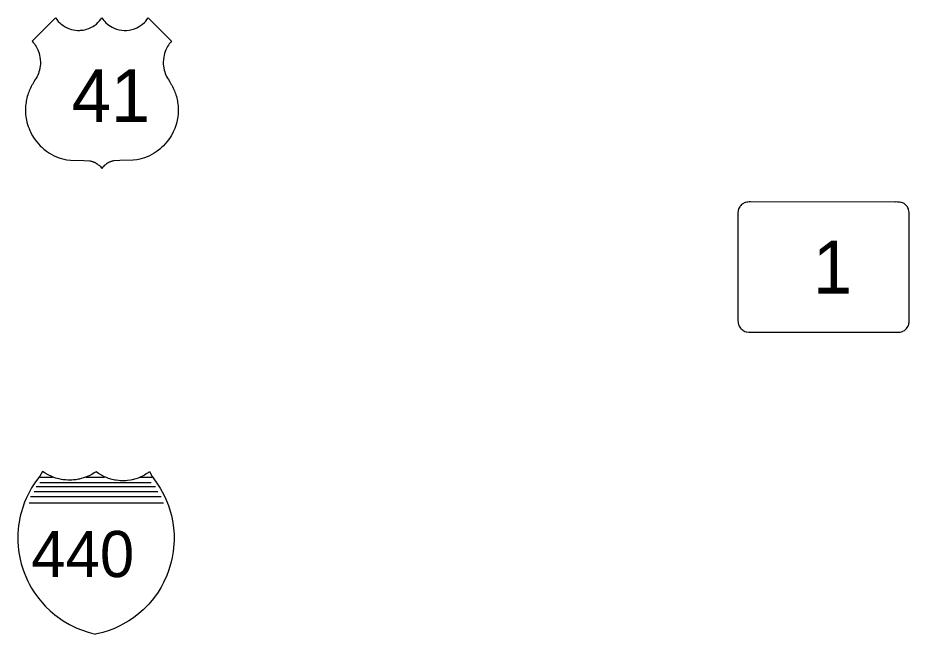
# Model space of a CAD drawing. Extents: x 1612280 to 1883141, y 560852 to 780851.
# Drawn here: x 1750959 to 1758104, y 653332 to 658270 of the extents above; entities that cross this region are included whole.
import ezdxf

# ---------------------------------------------------------------- set-up
doc = ezdxf.new("R2010")
doc.units = 0
for name, color, linetype in [('DESIGN - ROW - Slope Lines', 7, 'Continuous'), ('SURVEY - DRAINAGE - Bridge Deck with Text', 7, 'Continuous'), ('SURVEY - DRAINAGE - Bridge Hydraulic Data with Text', 7, 'Continuous')]:
    doc.layers.add(name, color=color, linetype=linetype)

msp = doc.modelspace()

# ---------------------------------------------------------------- linework, layer by layer
at = {"layer": 'DESIGN - ROW - Slope Lines'}
msp.add_line((1756730.7, 656692.9), (1756730.7, 655861.1), dxfattribs=at)
msp.add_line((1756730.7, 656692.9), (1756730.7, 655861.1), dxfattribs=at)
for points in [[(1758103.6, 656682.5), (1758103.5, 656690.2), (1758103.3, 656698.3), (1758102.3, 656712.9), (1758100.9, 656723.4), (1758099.1, 656734.2), (1758097.1, 656740.1), (1758093.9, 656746.7), (1758089.5, 656754.2), (1758084.1, 656761.6), (1758079.4, 656767), (1758073.5, 656772.6), (1758068.8, 656776.4), (1758062.4, 656780.9), (1758057.4, 656783.9), (1758049.1, 656787.9), (1758043, 656790), (1758035.8, 656791.4), (1758026.5, 656792.8), (1758018.4, 656793.6), (1758009.7, 656794.2), (1757997.4, 656794.3), (1757988, 656793.6), (1756830.7, 656794.3), (1756821.3, 656794.3), (1756811, 656793.6), (1756801.9, 656792.5), (1756792.8, 656790.8), (1756788.5, 656789.5), (1756781.3, 656786.4), (1756774.9, 656783.1), (1756769.6, 656779.8), (1756760.7, 656773), (1756754.6, 656767.2), (1756749.5, 656761.3), (1756745.6, 656756), (1756739.8, 656746.4), (1756736.4, 656739.1), (1756734.5, 656733.9), (1756733.8, 656730.1), (1756733.3, 656726.8), (1756732.4, 656719.6), (1756731.3, 656710.2), (1756730.9, 656702.3), (1756730.8, 656695.6), (1756730.7, 656677.7)], [(1758103.6, 656682.5), (1758103.5, 656690.2), (1758103.3, 656698.3), (1758102.3, 656712.9), (1758100.9, 656723.4), (1758099.1, 656734.2), (1758097.1, 656740.1), (1758093.9, 656746.7), (1758089.5, 656754.2), (1758084.1, 656761.6), (1758079.4, 656767), (1758073.5, 656772.6), (1758068.8, 656776.4), (1758062.4, 656780.9), (1758057.4, 656783.9), (1758049.1, 656787.9), (1758043, 656790), (1758035.8, 656791.4), (1758026.5, 656792.8), (1758018.4, 656793.6), (1758009.7, 656794.2), (1757997.4, 656794.3), (1757988, 656793.6), (1756830.7, 656794.3), (1756821.3, 656794.3), (1756811, 656793.6), (1756801.9, 656792.5), (1756792.8, 656790.8), (1756788.5, 656789.5), (1756781.3, 656786.4), (1756774.9, 656783.1), (1756769.6, 656779.8), (1756760.7, 656773), (1756754.6, 656767.2), (1756749.5, 656761.3), (1756745.6, 656756), (1756739.8, 656746.4), (1756736.4, 656739.1), (1756734.5, 656733.9), (1756733.8, 656730.1), (1756733.3, 656726.8), (1756732.4, 656719.6), (1756731.3, 656710.2), (1756730.9, 656702.3), (1756730.8, 656695.6), (1756730.7, 656677.7)], [(1757993.7, 655751.8), (1758014.4, 655752.1), (1758031.4, 655752.4), (1758041.7, 655754.8), (1758053.9, 655759.6), (1758065.1, 655766), (1758074, 655772.9), (1758082.1, 655780.9), (1758088.3, 655788.8), (1758094.3, 655798.6), (1758097.9, 655806.4), (1758100.5, 655813.4), (1758102.1, 655821), (1758102.9, 655829.2), (1758103.2, 655839.2), (1758103.6, 655862.5), (1758103.6, 656682.5)], [(1757993.7, 655751.8), (1758014.4, 655752.1), (1758031.4, 655752.4), (1758041.7, 655754.8), (1758053.9, 655759.6), (1758065.1, 655766), (1758074, 655772.9), (1758082.1, 655780.9), (1758088.3, 655788.8), (1758094.3, 655798.6), (1758097.9, 655806.4), (1758100.5, 655813.4), (1758102.1, 655821), (1758102.9, 655829.2), (1758103.2, 655839.2), (1758103.6, 655862.5), (1758103.6, 656682.5)], [(1756730.7, 655861.1), (1756730.9, 655852.1), (1756731.4, 655842), (1756732.2, 655832.5), (1756733.3, 655823.3), (1756734.7, 655814.1), (1756737.5, 655806.4), (1756740.9, 655799.2), (1756745.4, 655791.8), (1756750.8, 655784.5), (1756756.4, 655778.3), (1756763.7, 655771.7), (1756770.6, 655766.5), (1756778.6, 655761.7), (1756787.2, 655757.7), (1756796.1, 655754.6), (1756803.4, 655753.7), (1756818.3, 655752.5), (1756837.1, 655751.8), (1757993.7, 655751.8)], [(1756730.7, 655861.1), (1756730.9, 655852.1), (1756731.4, 655842), (1756732.2, 655832.5), (1756733.3, 655823.3), (1756734.7, 655814.1), (1756737.5, 655806.4), (1756740.9, 655799.2), (1756745.4, 655791.8), (1756750.8, 655784.5), (1756756.4, 655778.3), (1756763.7, 655771.7), (1756770.6, 655766.5), (1756778.6, 655761.7), (1756787.2, 655757.7), (1756796.1, 655754.6), (1756803.4, 655753.7), (1756818.3, 655752.5), (1756837.1, 655751.8), (1757993.7, 655751.8)]]:
    msp.add_lwpolyline(points, dxfattribs=at)
at = {"layer": 'SURVEY - DRAINAGE - Bridge Deck with Text'}
for points in [[(1751074.2, 658083.2), (1751261.7, 658269.6), (1751271.4, 658255.9), (1751283.7, 658241.1), (1751295.8, 658228.9), (1751307, 658219.1), (1751319.4, 658209.7), (1751332.2, 658201.3), (1751344.6, 658194.3), (1751359.2, 658187.4), (1751372.2, 658182.2), (1751388.6, 658177), (1751404.3, 658173.3), (1751420.8, 658170.7), (1751438.5, 658169.3), (1751446.5, 658169.1), (1751454.6, 658169.2), (1751462.4, 658169.6), (1751472.6, 658170.5), (1751482.9, 658172), (1751496.4, 658174.6), (1751508.9, 658177.8), (1751527.1, 658184), (1751544.3, 658191.5), (1751560.8, 658200.4), (1751574.7, 658209.4), (1751588.5, 658219.9), (1751601.7, 658231.8), (1751613.8, 658244.5), (1751625, 658258.4), (1751632.8, 658269.6), (1751639.7, 658259.7), (1751648.5, 658248.5), (1751656.4, 658239.5), (1751665.7, 658230.1), (1751677.4, 658219.7), (1751689.8, 658210.2), (1751703, 658201.6), (1751716.6, 658193.9), (1751732.6, 658186.4), (1751751.2, 658179.5), (1751772.5, 658173.9), (1751793.3, 658170.5), (1751811.5, 658169.2), (1751831.2, 658169.5), (1751851.5, 658171.6), (1751871.6, 658175.6), (1751894, 658182.4), (1751911.7, 658189.7), (1751926.3, 658197.1), (1751943.3, 658207.6), (1751957.5, 658218.2), (1751973.3, 658232.2), (1751984.1, 658243.5), (1751993.9, 658255.4), (1752004, 658269.7), (1752190.8, 658083.2)], [(1751074.2, 658083.2), (1751261.7, 658269.6), (1751271.4, 658255.9), (1751283.7, 658241.1), (1751295.8, 658228.9), (1751307, 658219.1), (1751319.4, 658209.7), (1751332.2, 658201.3), (1751344.6, 658194.3), (1751359.2, 658187.4), (1751372.2, 658182.2), (1751388.6, 658177), (1751404.3, 658173.3), (1751420.8, 658170.7), (1751438.5, 658169.3), (1751446.5, 658169.1), (1751454.6, 658169.2), (1751462.4, 658169.6), (1751472.6, 658170.5), (1751482.9, 658172), (1751496.4, 658174.6), (1751508.9, 658177.8), (1751527.1, 658184), (1751544.3, 658191.5), (1751560.8, 658200.4), (1751574.7, 658209.4), (1751588.5, 658219.9), (1751601.7, 658231.8), (1751613.8, 658244.5), (1751625, 658258.4), (1751632.8, 658269.6), (1751639.7, 658259.7), (1751648.5, 658248.5), (1751656.4, 658239.5), (1751665.7, 658230.1), (1751677.4, 658219.7), (1751689.8, 658210.2), (1751703, 658201.6), (1751716.6, 658193.9), (1751732.6, 658186.4), (1751751.2, 658179.5), (1751772.5, 658173.9), (1751793.3, 658170.5), (1751811.5, 658169.2), (1751831.2, 658169.5), (1751851.5, 658171.6), (1751871.6, 658175.6), (1751894, 658182.4), (1751911.7, 658189.7), (1751926.3, 658197.1), (1751943.3, 658207.6), (1751957.5, 658218.2), (1751973.3, 658232.2), (1751984.1, 658243.5), (1751993.9, 658255.4), (1752004, 658269.7), (1752190.8, 658083.2)], [(1751074.2, 658083.2), (1751083.3, 658072.5), (1751091.6, 658061.9), (1751099.2, 658050.7), (1751105.5, 658040.4), (1751112.3, 658028), (1751118.8, 658014.1), (1751124.4, 658000), (1751129.5, 657984.6), (1751133.4, 657970.2), (1751136.5, 657954.2), (1751138.8, 657936.5), (1751139.9, 657914.8), (1751139.6, 657898.4), (1751138.2, 657882.4), (1751136.1, 657868.4), (1751132.2, 657850.2), (1751128.3, 657836.4), (1751123.7, 657823.2), (1751118.8, 657811.1), (1751114, 657800.8), (1751106.3, 657787), (1751099, 657774.4), (1751088.5, 657756.8), (1751075.7, 657735.7), (1751072, 657729.7), (1751066, 657718.7), (1751059.5, 657705.5), (1751055.3, 657696.4), (1751050.5, 657685.1), (1751046.4, 657674.8), (1751042.5, 657663.8), (1751038.6, 657652.1), (1751034.9, 657639.5), (1751031.5, 657626.1), (1751028.9, 657614.9), (1751026.6, 657602.8), (1751024.7, 657590.9), (1751023, 657578.2), (1751021.8, 657566.6), (1751021, 657555.1), (1751020.5, 657544.2), (1751020.3, 657533.1), (1751020.4, 657520.6), (1751020.9, 657509), (1751021.9, 657494.5), (1751023.6, 657479.4), (1751025.8, 657464.1), (1751028.6, 657449.4), (1751032.3, 657433.1), (1751037.5, 657414), (1751042.2, 657399.4), (1751048.7, 657381.8), (1751054.6, 657368.2), (1751059.7, 657356.6), (1751067, 657342), (1751076.7, 657324.5), (1751085.9, 657309.8), (1751097.9, 657292.2), (1751110.4, 657275.9), (1751124.2, 657259.6), (1751138.7, 657244.3), (1751151.2, 657232.3), (1751168.1, 657217.6), (1751187.8, 657202.2), (1751212, 657185.9), (1751232.2, 657174.1), (1751251.7, 657164.2), (1751269.7, 657156.1), (1751290.5, 657148.1), (1751309.8, 657141.7), (1751329.2, 657136.4), (1751339, 657134.1), (1751351.7, 657132.4), (1751381.8, 657129.8), (1751487.4, 657126.5), (1751535.1, 657124), (1751539.6, 657123.5), (1751544.4, 657122.4), (1751549.6, 657121.1), (1751554.6, 657119.6), (1751559.4, 657118.1), (1751564, 657116.3), (1751569.3, 657114.2), (1751573.7, 657112.2), (1751578.8, 657109.7), (1751582.7, 657107.7), (1751586.7, 657105.4), (1751595.3, 657100), (1751604.4, 657093.3), (1751612.9, 657085.9), (1751620.6, 657078.4), (1751627, 657071.1), (1751632.5, 657062.8)], [(1751074.2, 658083.2), (1751083.3, 658072.5), (1751091.6, 658061.9), (1751099.2, 658050.7), (1751105.5, 658040.4), (1751112.3, 658028), (1751118.8, 658014.1), (1751124.4, 658000), (1751129.5, 657984.6), (1751133.4, 657970.2), (1751136.5, 657954.2), (1751138.8, 657936.5), (1751139.9, 657914.8), (1751139.6, 657898.4), (1751138.2, 657882.4), (1751136.1, 657868.4), (1751132.2, 657850.2), (1751128.3, 657836.4), (1751123.7, 657823.2), (1751118.8, 657811.1), (1751114, 657800.8), (1751106.3, 657787), (1751099, 657774.4), (1751088.5, 657756.8), (1751075.7, 657735.7), (1751072, 657729.7), (1751066, 657718.7), (1751059.5, 657705.5), (1751055.3, 657696.4), (1751050.5, 657685.1), (1751046.4, 657674.8), (1751042.5, 657663.8), (1751038.6, 657652.1), (1751034.9, 657639.5), (1751031.5, 657626.1), (1751028.9, 657614.9), (1751026.6, 657602.8), (1751024.7, 657590.9), (1751023, 657578.2), (1751021.8, 657566.6), (1751021, 657555.1), (1751020.5, 657544.2), (1751020.3, 657533.1), (1751020.4, 657520.6), (1751020.9, 657509), (1751021.9, 657494.5), (1751023.6, 657479.4), (1751025.8, 657464.1), (1751028.6, 657449.4), (1751032.3, 657433.1), (1751037.5, 657414), (1751042.2, 657399.4), (1751048.7, 657381.8), (1751054.6, 657368.2), (1751059.7, 657356.6), (1751067, 657342), (1751076.7, 657324.5), (1751085.9, 657309.8), (1751097.9, 657292.2), (1751110.4, 657275.9), (1751124.2, 657259.6), (1751138.7, 657244.3), (1751151.2, 657232.3), (1751168.1, 657217.6), (1751187.8, 657202.2), (1751212, 657185.9), (1751232.2, 657174.1), (1751251.7, 657164.2), (1751269.7, 657156.1), (1751290.5, 657148.1), (1751309.8, 657141.7), (1751329.2, 657136.4), (1751339, 657134.1), (1751351.7, 657132.4), (1751381.8, 657129.8), (1751487.4, 657126.5), (1751535.1, 657124), (1751539.6, 657123.5), (1751544.4, 657122.4), (1751549.6, 657121.1), (1751554.6, 657119.6), (1751559.4, 657118.1), (1751564, 657116.3), (1751569.3, 657114.2), (1751573.7, 657112.2), (1751578.8, 657109.7), (1751582.7, 657107.7), (1751586.7, 657105.4), (1751595.3, 657100), (1751604.4, 657093.3), (1751612.9, 657085.9), (1751620.6, 657078.4), (1751627, 657071.1), (1751632.5, 657062.8)], [(1752190.8, 658083.2), (1752181.7, 658072.6), (1752173.4, 658061.9), (1752165.8, 658050.7), (1752159.5, 658040.5), (1752152.7, 658028), (1752146.2, 658014.1), (1752140.6, 658000.1), (1752135.5, 657984.7), (1752131.6, 657970.2), (1752128.5, 657954.2), (1752126.2, 657936.5), (1752125.1, 657914.8), (1752125.4, 657898.4), (1752126.8, 657882.5), (1752128.9, 657868.5), (1752132.8, 657850.2), (1752136.7, 657836.4), (1752141.3, 657823.3), (1752146.2, 657811.2), (1752151, 657800.8), (1752158.8, 657787), (1752166, 657774.5), (1752176.5, 657756.8), (1752189.3, 657735.7), (1752193, 657729.8), (1752199, 657718.7), (1752205.5, 657705.6), (1752209.7, 657696.5), (1752214.5, 657685.1), (1752218.6, 657674.8), (1752222.5, 657663.8), (1752226.4, 657652.1), (1752230.1, 657639.5), (1752233.6, 657626.1), (1752236.1, 657614.9), (1752238.4, 657602.9), (1752240.3, 657590.9), (1752242, 657578.2), (1752243.2, 657566.7), (1752244.1, 657555.1), (1752244.6, 657544.2), (1752244.7, 657533.1), (1752244.6, 657520.6), (1752244.2, 657509.1), (1752243.1, 657494.5), (1752241.4, 657479.4), (1752239.2, 657464.1), (1752236.4, 657449.4), (1752232.8, 657433.1), (1752227.5, 657414), (1752222.8, 657399.5), (1752216.4, 657381.9), (1752210.4, 657368.2), (1752205.4, 657356.6), (1752198.1, 657342), (1752188.3, 657324.5), (1752179.2, 657309.8), (1752167.2, 657292.3), (1752154.6, 657275.9), (1752140.8, 657259.7), (1752126.3, 657244.3), (1752113.9, 657232.3), (1752097, 657217.6), (1752077.2, 657202.2), (1752053, 657186), (1752032.8, 657174.2), (1752013.3, 657164.2), (1751995.3, 657156.1), (1751974.5, 657148.1), (1751955.2, 657141.7), (1751935.9, 657136.4), (1751926, 657134.1), (1751913.3, 657132.5), (1751883.2, 657129.8), (1751777.6, 657126.5), (1751729.9, 657124), (1751725.5, 657123.5), (1751720.6, 657122.4), (1751715.5, 657121.1), (1751710.4, 657119.6), (1751705.7, 657118.1), (1751701.1, 657116.3), (1751695.8, 657114.2), (1751691.4, 657112.2), (1751686.2, 657109.7), (1751682.4, 657107.7), (1751678.3, 657105.4), (1751669.8, 657100), (1751660.7, 657093.3), (1751652.1, 657085.9), (1751644.5, 657078.4), (1751638.1, 657071.1), (1751632.5, 657062.8)], [(1752190.8, 658083.2), (1752181.7, 658072.6), (1752173.4, 658061.9), (1752165.8, 658050.7), (1752159.5, 658040.5), (1752152.7, 658028), (1752146.2, 658014.1), (1752140.6, 658000.1), (1752135.5, 657984.7), (1752131.6, 657970.2), (1752128.5, 657954.2), (1752126.2, 657936.5), (1752125.1, 657914.8), (1752125.4, 657898.4), (1752126.8, 657882.5), (1752128.9, 657868.5), (1752132.8, 657850.2), (1752136.7, 657836.4), (1752141.3, 657823.3), (1752146.2, 657811.2), (1752151, 657800.8), (1752158.8, 657787), (1752166, 657774.5), (1752176.5, 657756.8), (1752189.3, 657735.7), (1752193, 657729.8), (1752199, 657718.7), (1752205.5, 657705.6), (1752209.7, 657696.5), (1752214.5, 657685.1), (1752218.6, 657674.8), (1752222.5, 657663.8), (1752226.4, 657652.1), (1752230.1, 657639.5), (1752233.6, 657626.1), (1752236.1, 657614.9), (1752238.4, 657602.9), (1752240.3, 657590.9), (1752242, 657578.2), (1752243.2, 657566.7), (1752244.1, 657555.1), (1752244.6, 657544.2), (1752244.7, 657533.1), (1752244.6, 657520.6), (1752244.2, 657509.1), (1752243.1, 657494.5), (1752241.4, 657479.4), (1752239.2, 657464.1), (1752236.4, 657449.4), (1752232.8, 657433.1), (1752227.5, 657414), (1752222.8, 657399.5), (1752216.4, 657381.9), (1752210.4, 657368.2), (1752205.4, 657356.6), (1752198.1, 657342), (1752188.3, 657324.5), (1752179.2, 657309.8), (1752167.2, 657292.3), (1752154.6, 657275.9), (1752140.8, 657259.7), (1752126.3, 657244.3), (1752113.9, 657232.3), (1752097, 657217.6), (1752077.2, 657202.2), (1752053, 657186), (1752032.8, 657174.2), (1752013.3, 657164.2), (1751995.3, 657156.1), (1751974.5, 657148.1), (1751955.2, 657141.7), (1751935.9, 657136.4), (1751926, 657134.1), (1751913.3, 657132.5), (1751883.2, 657129.8), (1751777.6, 657126.5), (1751729.9, 657124), (1751725.5, 657123.5), (1751720.6, 657122.4), (1751715.5, 657121.1), (1751710.4, 657119.6), (1751705.7, 657118.1), (1751701.1, 657116.3), (1751695.8, 657114.2), (1751691.4, 657112.2), (1751686.2, 657109.7), (1751682.4, 657107.7), (1751678.3, 657105.4), (1751669.8, 657100), (1751660.7, 657093.3), (1751652.1, 657085.9), (1751644.5, 657078.4), (1751638.1, 657071.1), (1751632.5, 657062.8)]]:
    msp.add_lwpolyline(points, dxfattribs=at)
at = {"layer": 'SURVEY - DRAINAGE - Bridge Hydraulic Data with Text'}
for p, q in [((1751130.4, 654590.8), (1751237.1, 654590.8)), ((1751130.4, 654590.8), (1751237.1, 654590.8)), ((1751506.3, 654590.8), (1751653.6, 654590.8)), ((1751506.3, 654590.8), (1751653.6, 654590.8)), ((1751939, 654590.8), (1752038.9, 654590.8)), ((1751939, 654590.8), (1752038.9, 654590.8)), ((1751106.7, 654513.7), (1752062.6, 654513.7)), ((1751106.7, 654513.7), (1752062.6, 654513.7)), ((1751134.4, 654547.6), (1752028.6, 654547.6)), ((1751134.4, 654547.6), (1752028.6, 654547.6)), ((1751089.7, 654474.7), (1752081.7, 654474.7)), ((1751089.7, 654474.7), (1752081.7, 654474.7)), ((1751050.3, 654383.6), (1752127.5, 654383.7)), ((1751050.3, 654383.6), (1752127.5, 654383.7)), ((1751062, 654434.4), (1752107.3, 654434.4)), ((1751062, 654434.4), (1752107.3, 654434.4))]:
    msp.add_line(p, q, dxfattribs=at)
for points in [[(1751157.1, 654636), (1751134.5, 654597.1), (1751115.5, 654572.7), (1751096, 654545.3), (1751085.5, 654529.6), (1751069.9, 654504.5), (1751054.1, 654476.7), (1751036.1, 654441.3), (1751025.3, 654417.7), (1751013.5, 654389.4), (1750995.6, 654338.9), (1750987.5, 654311.5), (1750981.3, 654287.5), (1750975.8, 654263.3), (1750969.6, 654230.3), (1750965.6, 654203), (1750962.2, 654171.2), (1750960, 654138.2), (1750959.1, 654098.9), (1750959.7, 654070.1), (1750961.5, 654039.9), (1750965.3, 654003.3), (1750969.9, 653972.4), (1750977.6, 653932.6), (1750987.1, 653894.1), (1750998.6, 653855.8), (1751008.8, 653826.8), (1751022, 653793.7), (1751038.8, 653756.9), (1751052.3, 653730.5), (1751068.7, 653701.3), (1751088.3, 653670), (1751124.1, 653619.9), (1751150.9, 653587.2), (1751181.8, 653553.5), (1751217.9, 653518.6), (1751255.4, 653486.8), (1751322.7, 653438.7), (1751374.4, 653408.5), (1751433.4, 653379.9), (1751469.5, 653365.4), (1751522.7, 653347.5), (1751559.5, 653337.6), (1751582.4, 653332)], [(1751157.1, 654636), (1751134.5, 654597.1), (1751115.5, 654572.7), (1751096, 654545.3), (1751085.5, 654529.6), (1751069.9, 654504.5), (1751054.1, 654476.7), (1751036.1, 654441.3), (1751025.3, 654417.7), (1751013.5, 654389.4), (1750995.6, 654338.9), (1750987.5, 654311.5), (1750981.3, 654287.5), (1750975.8, 654263.3), (1750969.6, 654230.3), (1750965.6, 654203), (1750962.2, 654171.2), (1750960, 654138.2), (1750959.1, 654098.9), (1750959.7, 654070.1), (1750961.5, 654039.9), (1750965.3, 654003.3), (1750969.9, 653972.4), (1750977.6, 653932.6), (1750987.1, 653894.1), (1750998.6, 653855.8), (1751008.8, 653826.8), (1751022, 653793.7), (1751038.8, 653756.9), (1751052.3, 653730.5), (1751068.7, 653701.3), (1751088.3, 653670), (1751124.1, 653619.9), (1751150.9, 653587.2), (1751181.8, 653553.5), (1751217.9, 653518.6), (1751255.4, 653486.8), (1751322.7, 653438.7), (1751374.4, 653408.5), (1751433.4, 653379.9), (1751469.5, 653365.4), (1751522.7, 653347.5), (1751559.5, 653337.6), (1751582.4, 653332)], [(1752015.5, 654634.7), (1752003, 654625.4), (1751988.5, 654615.6), (1751973.5, 654606.6), (1751957.5, 654598), (1751945.1, 654592), (1751923.3, 654583), (1751905.4, 654576.8), (1751876.7, 654569), (1751861.5, 654566), (1751837.1, 654562.5), (1751824.3, 654561.4), (1751808.2, 654560.6), (1751787.9, 654560.8), (1751779.4, 654561.2), (1751765.4, 654562.3), (1751748.4, 654564.4), (1751735.4, 654566.6), (1751714.6, 654571.1), (1751687, 654579.3), (1751668.9, 654586), (1751653.6, 654592.6), (1751629.4, 654604.9), (1751605.2, 654619.8), (1751586.3, 654633.4), (1751571.4, 654623.5), (1751551.8, 654611.9), (1751531.5, 654601.5), (1751515.9, 654594.5), (1751501.5, 654588.9), (1751485.2, 654583.3), (1751466, 654577.8), (1751454, 654574.9), (1751443.5, 654572.7), (1751424.4, 654569.5), (1751405, 654567.4), (1751391.1, 654566.4), (1751377.2, 654566), (1751358.9, 654566.3), (1751341.9, 654567.4), (1751322.6, 654569.5), (1751309.7, 654571.6), (1751290.6, 654575.5), (1751275.5, 654579.2), (1751263.8, 654582.7), (1751248.8, 654587.7), (1751237.1, 654592.1), (1751226.2, 654596.7), (1751208.9, 654604.7), (1751196.7, 654611), (1751185.5, 654617.4), (1751170.2, 654626.9), (1751157.1, 654636)], [(1752015.5, 654634.7), (1752003, 654625.4), (1751988.5, 654615.6), (1751973.5, 654606.6), (1751957.5, 654598), (1751945.1, 654592), (1751923.3, 654583), (1751905.4, 654576.8), (1751876.7, 654569), (1751861.5, 654566), (1751837.1, 654562.5), (1751824.3, 654561.4), (1751808.2, 654560.6), (1751787.9, 654560.8), (1751779.4, 654561.2), (1751765.4, 654562.3), (1751748.4, 654564.4), (1751735.4, 654566.6), (1751714.6, 654571.1), (1751687, 654579.3), (1751668.9, 654586), (1751653.6, 654592.6), (1751629.4, 654604.9), (1751605.2, 654619.8), (1751586.3, 654633.4), (1751571.4, 654623.5), (1751551.8, 654611.9), (1751531.5, 654601.5), (1751515.9, 654594.5), (1751501.5, 654588.9), (1751485.2, 654583.3), (1751466, 654577.8), (1751454, 654574.9), (1751443.5, 654572.7), (1751424.4, 654569.5), (1751405, 654567.4), (1751391.1, 654566.4), (1751377.2, 654566), (1751358.9, 654566.3), (1751341.9, 654567.4), (1751322.6, 654569.5), (1751309.7, 654571.6), (1751290.6, 654575.5), (1751275.5, 654579.2), (1751263.8, 654582.7), (1751248.8, 654587.7), (1751237.1, 654592.1), (1751226.2, 654596.7), (1751208.9, 654604.7), (1751196.7, 654611), (1751185.5, 654617.4), (1751170.2, 654626.9), (1751157.1, 654636)], [(1752015.5, 654634.7), (1752035.3, 654593.9), (1752068.4, 654550.3), (1752100.5, 654501.1), (1752129.3, 654448.7), (1752146.3, 654412.5), (1752166.5, 654361.5), (1752180.9, 654317.1), (1752190.2, 654282.3), (1752201.6, 654226), (1752207.6, 654181.5), (1752211.2, 654133.8), (1752211.8, 654081.7), (1752205.1, 653994.9), (1752197.1, 653947), (1752186.7, 653901.5), (1752168, 653840.2), (1752152.9, 653800.7), (1752127.7, 653745.8), (1752107.3, 653707.9), (1752083, 653668.6), (1752047.3, 653618.8), (1752008.9, 653573.2), (1751962.6, 653526.2), (1751928.6, 653496.4), (1751885.7, 653463.4), (1751848.9, 653438.6), (1751776.4, 653397.8), (1751734.1, 653378.5), (1751690, 653361.4), (1751641.5, 653346.1), (1751582.4, 653332)], [(1752015.5, 654634.7), (1752035.3, 654593.9), (1752068.4, 654550.3), (1752100.5, 654501.1), (1752129.3, 654448.7), (1752146.3, 654412.5), (1752166.5, 654361.5), (1752180.9, 654317.1), (1752190.2, 654282.3), (1752201.6, 654226), (1752207.6, 654181.5), (1752211.2, 654133.8), (1752211.8, 654081.7), (1752205.1, 653994.9), (1752197.1, 653947), (1752186.7, 653901.5), (1752168, 653840.2), (1752152.9, 653800.7), (1752127.7, 653745.8), (1752107.3, 653707.9), (1752083, 653668.6), (1752047.3, 653618.8), (1752008.9, 653573.2), (1751962.6, 653526.2), (1751928.6, 653496.4), (1751885.7, 653463.4), (1751848.9, 653438.6), (1751776.4, 653397.8), (1751734.1, 653378.5), (1751690, 653361.4), (1751641.5, 653346.1), (1751582.4, 653332)]]:
    msp.add_lwpolyline(points, dxfattribs=at)

# ---------------------------------------------------------------- texts
at = {"layer": 'DESIGN - ROW - Slope Lines'}
msp.add_text('1', height=422.4, rotation=0.00108, dxfattribs=at).set_placement((1757332.1, 656061))
msp.add_text('1', height=422.4, rotation=0.00108, dxfattribs=at).set_placement((1757332.1, 656061))
at = {"layer": 'SURVEY - DRAINAGE - Bridge Deck with Text'}
msp.add_text('41', height=422.4, rotation=0.00128, dxfattribs=at).set_placement((1751391.4, 657435.8))
msp.add_text('41', height=422.4, rotation=0.00128, dxfattribs=at).set_placement((1751391.4, 657435.8))
at = {"layer": 'SURVEY - DRAINAGE - Bridge Hydraulic Data with Text'}
msp.add_text('440', height=369.6, rotation=0.00131, dxfattribs=at).set_placement((1751067.2, 653789.3))
msp.add_text('440', height=369.6, rotation=0.00131, dxfattribs=at).set_placement((1751067.2, 653789.3))

doc.saveas('drawing.dxf')
